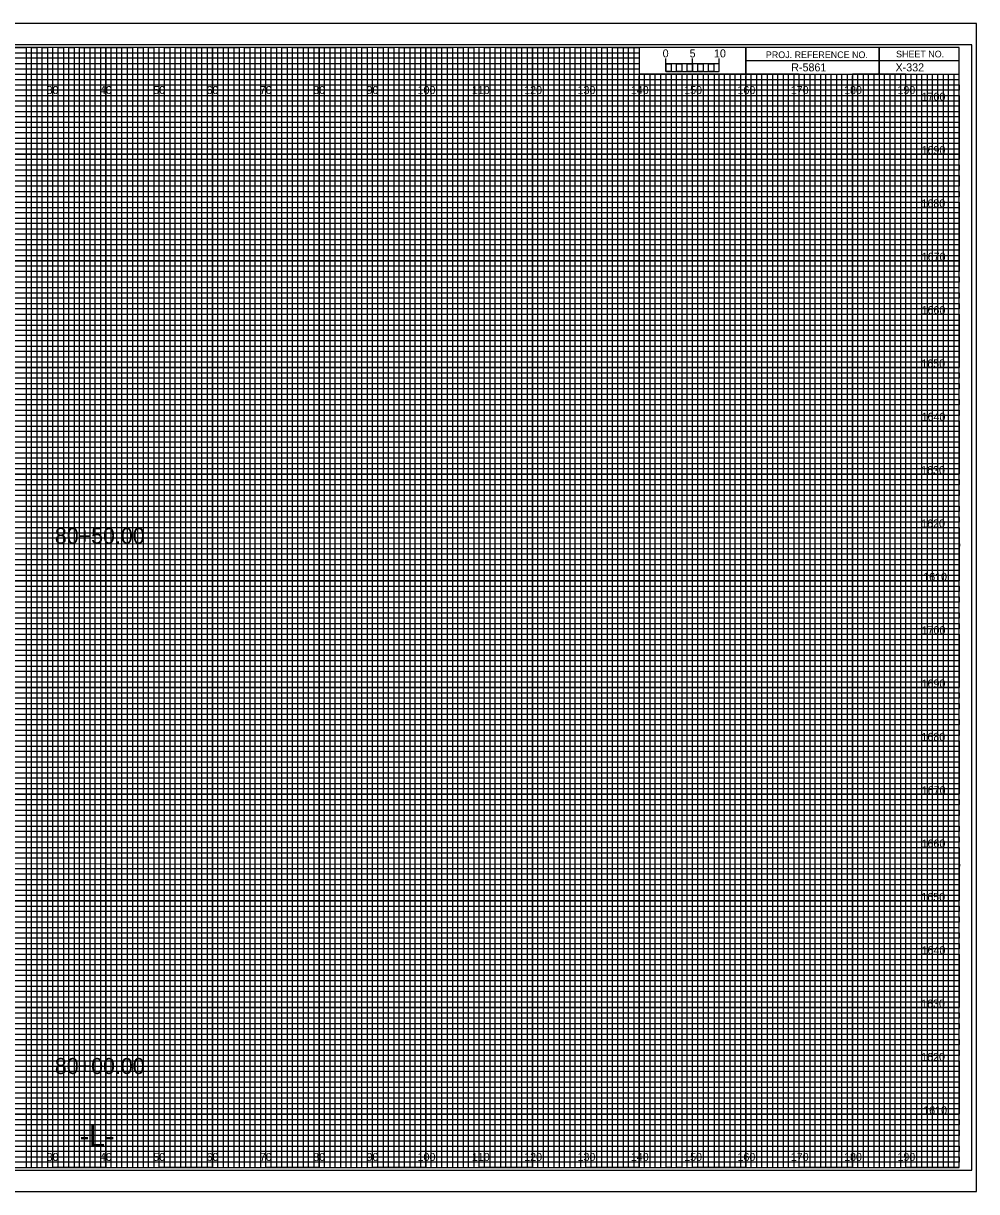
# Model space of a CAD drawing. Extents: x -13 to 1780, y -15 to 3284.
# Drawn here: x 144.5 to 323.3, y -4.5 to 214.5 of the extents above; entities that cross this region are included whole.
import ezdxf

# ---------------------------------------------------------------- set-up
doc = ezdxf.new("R2010")
doc.units = 0
for name, color, linetype in [('Exist CMT Pavement', 7, 'Continuous'), ('Prop Horizontal Alignment', 7, 'Continuous'), ('Prop Retaining Wall', 7, 'Continuous'), ('Prop SS Cut Line', 7, 'Continuous'), ('Prop SS Fill Line', 7, 'Continuous'), ('Prop SS Transition Line', 7, 'Continuous'), ('Prop XS Bar Scale Labels', 7, 'Continuous'), ('Prop XS DDE', 7, 'Continuous'), ('Prop XS Earthwork Shape', 7, 'Continuous'), ('Prop XS Noise Wall', 7, 'Continuous'), ('Prop XS Retaining Wall', 7, 'Continuous'), ('Prop XS Station Labels', 7, 'Continuous'), ('Raster_Level_0', 7, 'Continuous'), ('Scratch_Level_3', 7, 'Continuous'), ('Scratch_Level_7', 7, 'Continuous'), ('Typical Bridge Rail CELL', 7, 'Continuous'), ('Typical Median Barrier CELL', 7, 'Continuous')]:
    doc.layers.add(name, color=color, linetype=linetype)

msp = doc.modelspace()

# ---------------------------------------------------------------- linework, layer by layer
at = {"layer": 'Prop Retaining Wall'}
for p, q in [((305, 210), (305, 205)), ((305, 205), (305, 210)), ((280, 207.5), (280, 205)), ((320, 207.49), (280, 207.49)), ((280, 205), (320, 205))]:
    msp.add_line(p, q, dxfattribs=at)
for points in [[(320, 210), (0, 210), (0, 0), (320, 0)], [(280, 210), (260, 210), (260, 205.03), (280, 205.03)], [(320, 210), (280, 210), (280, 205), (320, 205)]]:
    msp.add_lwpolyline(points, close=True, dxfattribs=at)
at = {"layer": 'Prop SS Cut Line'}
for points in [[(135, 210), (145, 210), (145, 0), (155, 0), (155, 210), (165, 210), (165, 0), (175, 0), (175, 210), (185, 210), (185, 0), (195, 0), (195, 210), (205, 210), (205, 0), (215, 0), (215, 210), (225, 210), (225, 0), (235, 0), (235, 210), (245, 210), (245, 0), (255, 0), (255, 210), (259.93, 210), (260, 210), (260, 205), (264.99, 205), (264.99, 0), (275, 0), (275, 205), (285, 205), (285, 0), (295, 0), (295, 205), (305, 205), (305, 0), (315, 0), (315, 205)], [(0, 205), (275, 205)], [(0, 185), (320, 185), (320, 195), (0, 195)], [(0, 165), (320, 165), (320, 175), (0, 175)], [(0, 145), (320, 145), (320, 155), (0, 155)], [(0, 125), (320, 125), (320, 135), (0, 135)], [(0, 105), (320, 105), (320, 115), (0, 115)], [(0, 85), (320, 85), (320, 95), (0, 95)], [(0, 65), (320, 65), (320, 75), (0, 75)], [(0, 45), (320, 45), (320, 55), (0, 55)], [(0, 25), (320, 25), (320, 35), (0, 35)], [(0, 5), (320, 5), (320, 15), (0, 15)]]:
    msp.add_lwpolyline(points, dxfattribs=at)
at = {"layer": 'Prop SS Fill Line'}
for p, q in [((150, 210), (140, 210)), ((150, 0), (150, 210)), ((170, 210), (160, 210)), ((160, 210), (160, 0)), ((170, 0), (170, 210)), ((190, 210), (180, 210)), ((180, 210), (180, 0)), ((190, 0), (190, 210)), ((210, 210), (200, 210)), ((200, 210), (200, 0)), ((210, 0), (210, 210)), ((230, 210), (220, 210)), ((220, 210), (220, 0)), ((230, 0), (230, 210)), ((250, 210), (240, 210)), ((240, 210), (240, 0)), ((250, 0), (250, 210)), ((260, 210), (260, 0)), ((270, 0), (270, 205)), ((290, 205), (280, 205)), ((280, 205), (280, 0)), ((290, 0), (290, 205)), ((310, 205), (300, 205)), ((300, 205), (300, 0)), ((310, 0), (310, 205)), ((160, 0), (150, 0)), ((180, 0), (170, 0)), ((200, 0), (190, 0)), ((220, 0), (210, 0)), ((240, 0), (230, 0)), ((260, 0), (250, 0)), ((280, 0), (270, 0)), ((300, 0), (290, 0)), ((320, 0), (310, 0)), ((320, 0), (320, 0))]:
    msp.add_line(p, q, dxfattribs=at)
for points in [[(0, 200), (320, 200), (320, 190), (0, 190)], [(0, 180), (320, 180), (320, 170), (0, 170)], [(0, 160), (320, 160), (320, 150), (0, 150)], [(0, 140), (320, 140), (320, 130), (0, 130)], [(0, 120), (320, 120), (320, 110), (0, 110)], [(0, 100), (320, 100), (320, 90), (0, 90)], [(0, 80), (320, 80), (320, 70), (0, 70)], [(0, 60), (320, 60), (320, 50), (0, 50)], [(0, 40), (320, 40), (320, 30), (0, 30)], [(0, 20), (320, 20), (320, 10), (0, 10)]]:
    msp.add_lwpolyline(points, dxfattribs=at)
at = {"layer": 'Prop SS Transition Line'}
for p, q in [((0, 209), (260, 209)), ((260, 209), (260, 207.98)), ((260, 207.98), (0, 207.98)), ((0, 207), (260, 207)), ((260, 205.89), (0, 205.89)), ((260, 207), (260, 205.89)), ((0, 204), (320, 204))]:
    msp.add_line(p, q, dxfattribs=at)
for points in [[(0, 203), (270, 203), (320, 203), (320, 202), (0, 202)], [(0, 201), (320, 201), (320, 199), (0, 199)], [(0, 198), (320, 198), (320, 197), (0, 196.98)], [(0, 196), (320, 196), (320, 194), (0, 194)], [(0, 193), (320, 193), (320, 192), (0, 192)], [(0, 191), (320, 191), (320, 189), (0, 189)], [(0, 188), (320, 188), (320, 187), (0, 187)], [(0, 186), (320, 186), (320, 184), (0, 184)], [(0, 183), (320, 183), (320, 182), (0, 182)], [(0, 181), (320, 181), (320, 179), (0, 179)], [(0, 178), (320, 178), (320, 177), (0, 177)], [(0, 176), (320, 176), (320, 173.95), (320, 173), (320, 172), (0, 172)], [(0, 174), (320, 174), (320, 173), (0, 173)], [(0, 171), (320, 171), (320, 169), (0, 169.03)], [(0, 169.03), (320, 169), (320, 168), (0, 168)], [(0, 167), (320, 167), (320, 166), (0, 166)], [(0, 164), (320, 164), (320, 163), (0, 163)], [(0, 162), (320, 162), (320, 161), (0, 161)], [(-0.07, 158.89), (320, 158.89), (320, 157.88), (-0.07, 157.88)], [(0, 157), (320, 157), (320, 156), (0, 156)], [(0, 154), (320, 154), (320, 153), (0, 153)], [(0, 152), (320, 152), (320, 151), (0, 151)], [(0, 149), (320, 149), (320, 148), (0, 148)], [(0, 147), (320, 147), (320, 146), (0, 146)], [(0, 144), (320, 144), (320, 143), (0, 143)], [(0, 142), (320, 142), (320, 141), (0, 141)], [(0, 139), (320, 139), (319.99, 137.98), (0, 138)], [(0, 137), (320, 137), (320, 136), (0, 136)], [(0, 134), (320, 134), (320, 133), (0, 133)], [(0, 132), (320, 132), (320, 131), (0, 131)], [(0, 129), (320, 129), (320, 128), (0, 128)], [(0, 127), (320, 127), (320, 126), (0, 126)], [(0, 124), (320, 124), (320, 123), (0, 123)], [(0, 122), (320, 122), (320, 121), (0, 121)], [(0, 119), (320, 119), (320, 118), (0, 118)], [(0, 116.99), (320.07, 116.91), (320, 116), (0, 116)], [(0, 114), (320, 114), (320, 113), (0, 113)], [(0, 112), (320, 112), (320, 111), (0, 111)], [(0, 109), (320, 109), (320, 108), (0, 108)], [(0, 107), (320, 107), (320, 106), (0, 106)], [(0, 104), (320, 104), (320, 103), (0, 103)], [(0, 102), (320, 102), (320, 101), (0, 101)], [(0, 99), (320, 99), (320, 98), (0, 98)], [(0, 97), (320, 97), (320, 96), (0, 96)], [(0, 94), (320, 94), (320, 93), (0, 93)], [(0, 92), (320, 92), (320, 91), (0, 91)], [(0, 89), (320, 89), (320, 88), (0, 88)], [(0, 87), (320, 87), (320, 86), (0, 86)], [(0, 84), (320, 84), (320, 83), (0, 83)], [(0, 82), (320, 82), (320, 81), (0, 81)], [(0, 79), (320, 79), (319.99, 77.98), (0, 78)], [(0, 77), (320, 77), (320, 76), (0, 76)], [(0, 74), (320, 74), (320, 73), (0, 73)], [(0, 72), (320, 72), (320, 71), (0, 71)], [(0, 69), (320, 69), (320, 68), (0, 68)], [(0, 67), (320, 67), (320, 66), (0, 66)], [(0, 64), (320, 64), (320, 63), (0, 63)], [(0, 62), (320, 62), (320, 61), (0, 61)], [(0, 59), (320, 59), (320, 58), (0, 58)], [(0, 56.99), (320.07, 56.91), (320, 56), (0, 56)], [(0, 54), (320, 54), (320, 53), (0, 53)], [(0, 52), (320, 52), (320, 51), (0, 51)], [(0, 49), (320, 49), (320, 48), (0, 48)], [(0, 47), (320, 47), (320, 46), (0, 46)], [(0, 44), (320, 44), (320, 43), (0, 43)], [(0, 42), (320, 42), (320, 41), (0, 41)], [(0, 39), (320, 39), (320, 38), (0, 38)], [(0, 37), (320, 37), (320, 36), (0, 36)], [(0, 34), (320, 34), (320, 33), (0, 33)], [(0, 32), (320, 32), (320, 31), (0, 31)], [(0, 29), (320, 29), (320, 28), (0, 28)], [(0, 27), (320, 27), (320, 26), (0, 26)], [(0, 24), (320, 24), (320, 23), (0, 23)], [(0, 22), (320, 22), (320, 21), (0, 21)], [(0, 19), (320, 19), (320, 18), (0, 18)], [(0, 17), (320, 17), (320, 16), (0, 16)], [(0, 14), (320, 14), (320, 13), (0, 13)], [(0, 12), (320, 12), (320, 11), (0, 11)], [(0, 9), (320, 9), (320, 8), (0, 8)], [(0, 7), (320, 7), (320, 6), (0, 6)], [(0, 4), (320, 4), (320, 3), (0, 3)], [(0, 2), (320, 2), (320, 1), (0, 1)]]:
    msp.add_lwpolyline(points, dxfattribs=at)
at = {"layer": 'Prop XS Earthwork Shape'}
msp.add_lwpolyline([(-13.4, -4.5), (323.3, -4.5), (323.3, 214.5), (-13.4, 214.5)], close=True, dxfattribs=at)
at = {"layer": 'Prop XS Noise Wall'}
for p, q in [((150, 0), (150, 210)), ((160, 0), (160, 210)), ((170, 0), (170, 210)), ((180, 0), (180, 210)), ((190, 0), (190, 210)), ((200, 0), (200, 210)), ((210, 0), (210, 210)), ((220, 0), (220, 210)), ((230, 0), (230, 210)), ((240, 0), (240, 210)), ((250, 0), (250, 210)), ((260, 0), (260, 204.69)), ((270, 0), (270, 204.69)), ((280, 0), (280, 204.69)), ((290, 0), (290, 204.69)), ((300, 0), (300, 204.69)), ((310, 0), (310, 204.69)), ((0, 200), (320, 200)), ((0, 190), (320, 190)), ((0, 180), (320, 180)), ((0, 170), (320, 170)), ((0, 160), (320, 160)), ((0, 150), (320, 150)), ((0, 140), (320, 140)), ((0, 130), (320, 130)), ((0, 120), (320, 120)), ((0, 110), (320, 110)), ((0, 100), (320, 100)), ((0, 90), (320, 90)), ((0, 80), (320, 80)), ((0, 70), (320, 70)), ((0, 60), (320, 60)), ((0, 50), (320, 50)), ((0, 40), (320, 40)), ((0, 30), (320, 30)), ((0, 20), (320, 20)), ((0, 10), (320, 10))]:
    msp.add_line(p, q, dxfattribs=at)
at = {"layer": 'Prop XS Retaining Wall'}
for p, q in [((265, 205.49), (265, 207.9)), ((265, 206.9), (265, 207.9)), ((270, 205.49), (270, 207.9)), ((275, 205.49), (275, 207.9)), ((275, 206.9), (275, 207.9))]:
    msp.add_line(p, q, dxfattribs=at)
for points in [[(275, 206.9), (265, 206.9), (265, 205.49), (275, 205.49)], [(265, 206.9), (266, 206.9), (266, 205.49), (265, 205.49)], [(267, 206.9), (268, 206.9), (268, 205.49), (267, 205.49)], [(269, 206.9), (270, 206.9), (270, 205.49), (269, 205.49)], [(271, 206.9), (272, 206.9), (272, 205.49), (271, 205.49)], [(273, 206.9), (274, 206.9), (274, 205.49), (273, 205.49)]]:
    msp.add_lwpolyline(points, close=True, dxfattribs=at)
at = {"layer": 'Prop XS Station Labels'}
for p, q in [((323.3, 214.5), (-13.4, 214.5)), ((-13.4, -4.5), (323.3, -4.5))]:
    msp.add_line(p, q, dxfattribs=at)
at = {"layer": 'Scratch_Level_7'}
msp.add_lwpolyline([(-10.8, -0.5), (322.4, -0.5), (322.4, 210.5), (-10.8, 210.5)], close=True, dxfattribs=at)
at = {"layer": 'Typical Bridge Rail CELL'}
for p, q in [((267, 205), (266.01, 205)), ((266.01, 205), (266.01, 0)), ((267, 0), (267, 205)), ((269, 205), (268, 205)), ((268, 205), (268, 0)), ((269, 0), (269, 205)), ((266.01, 0), (265, 0)), ((268, 0), (267, 0))]:
    msp.add_line(p, q, dxfattribs=at)
for points in [[(145, 0), (146, 0), (146, 210), (147, 210), (147, 0)], [(147, 0), (148, 0), (148, 210), (149, 210), (149, 0)], [(150, 0), (151, 0), (151, 210), (152, 210), (152, 0)], [(152, 0), (153, 0), (153, 210), (154, 210), (154, 0)], [(155, 0), (156, 0), (156, 210), (157, 210), (157, 0)], [(157, 0), (158, 0), (158, 210), (159, 210), (159, 0)], [(160, 0), (161, 0), (161, 210), (162, 210), (162, 0)], [(162, 0), (163, 0), (163, 210), (164, 210), (164, 0)], [(165, 0), (166, 0), (166, 210), (167, 210), (167, 0)], [(167, 0), (168, 0), (168, 210), (169, 210), (169, 0)], [(170, 0), (171, 0), (171, 210), (172, 210), (172, 0)], [(172, 0), (173, 0), (173, 210), (174, 210), (174, 0)], [(175, 0), (176, 0), (176, 210), (177, 210), (177, 0)], [(177, 0), (178, 0), (178, 210), (179, 210), (179, 0)], [(180, 0), (181, 0), (181, 210), (182, 210), (182, 0)], [(182, 0), (183, 0), (183, 210), (184, 210), (184, 0)], [(185, 0), (186, 0), (186, 210), (187, 210), (187, 0)], [(187, 0), (188, 0), (188, 210), (189, 210), (189, 0)], [(190, 0), (191, 0), (191, 210), (192, 210), (192, 0)], [(192, 0), (193, 0), (193, 210), (194, 210), (194, 0)], [(195, 0), (196, 0), (196, 210), (197, 210), (197, 0)], [(197, 0), (198, 0), (198, 210), (199, 210), (199, 0)], [(200, 0), (201, 0), (201, 210), (202, 210), (202, 0)], [(202, 0), (203, 0), (203, 210), (204, 210), (204, 0)], [(205, 0), (206, 0), (206, 210), (207, 210), (207, 0)], [(207, 0), (208, 0), (208, 210), (209, 210), (209, 0)], [(210, 0), (211, 0), (211, 210), (212, 210), (212, 0)], [(212, 0), (213, 0), (213, 210), (214, 210), (214, 0)], [(215, 0), (216, 0), (216, 210), (217, 210), (217, 0)], [(217, 0), (218, 0), (218, 210), (219, 210), (219, 0)], [(220, 0), (221, 0), (221, 210), (222, 210), (222, 0)], [(222, 0), (223, 0), (223, 210), (224, 210), (224, 0)], [(225, 0), (226, 0), (226, 210), (227, 210), (227, 0)], [(227, 0), (228, 0), (228, 210), (229, 210), (229, 0)], [(230, 0), (231, 0), (231, 210), (232, 210), (232, 0)], [(232, 0), (233, 0), (233, 210), (234, 210), (234, 0)], [(235, 0), (236, 0), (236, 210), (237, 210), (237, 0)], [(237, 0), (238, 0), (238, 210), (239, 210), (239, 0)], [(240, 0), (241, 0), (241, 210), (242, 210), (242, 0)], [(242, 0), (243, 0), (243, 210), (244, 210), (244, 0)], [(245, 0), (246, 0), (246, 210), (247, 210), (247, 0)], [(247, 0), (248, 0), (248, 210), (249, 210), (249, 0)], [(250, 0), (251, 0), (251, 210), (252, 210), (252, 0)], [(252, 0), (253, 0), (253, 210), (254, 210), (254, 0)], [(255, 0), (256, 0), (256, 210), (257, 210), (257, 0)], [(257, 0), (258, 0), (258, 210), (259, 210), (259, 0)], [(260, 0), (261, 0), (261, 205), (262.02, 205), (262.02, 0)], [(262, 0), (263, 0), (263, 205), (263.99, 205), (263.99, 0)], [(270, 0), (270.98, 0), (270.98, 205), (272, 205), (272, 0)], [(272, 0), (273, 0), (273, 205), (274.05, 205), (274.05, 0)], [(275, 0), (276, 0), (276, 205), (277, 205), (277, 0)], [(277, 0), (278, 0), (278, 205), (279, 205), (279, 0)], [(280, 0), (281, 0), (281, 205), (282, 205), (282, 0)], [(282, 0), (283, 0), (283, 205), (284, 205), (284, 0)], [(285, 0), (286, 0), (286, 205), (287, 205), (287, 0)], [(287, 0), (288, 0), (288, 205), (289, 205), (289, 0)], [(290, 0), (291, 0), (291, 205), (292, 205), (292, 0)], [(292, 0), (293, 0), (293, 205), (294, 205), (294, 0)], [(295, 0), (296, 0), (296, 205), (297, 205), (297, 0)], [(297, 0), (298, 0), (298, 205), (299, 205), (299, 0)], [(300, 0), (301, 0), (301, 205), (302, 205), (302, 0)], [(302, 0), (303, 0), (303, 205), (304, 205), (304, 0)], [(305, 0), (306, 0), (306, 205), (307, 205), (307, 0)], [(307, 0), (308, 0), (308, 205), (309, 205), (309, 0)], [(310, 0), (311, 0), (311, 205), (312, 205), (312, 0)], [(312, 0), (313, 0), (313, 205), (314, 205), (314, 0)], [(315, 0), (316, 0), (316, 205), (317, 205), (317, 0)], [(317, 0), (318, 0), (318, 205), (319, 205), (319, 0)]]:
    msp.add_lwpolyline(points, dxfattribs=at)

# ---------------------------------------------------------------- texts
at = {"layer": 'Exist CMT Pavement'}
msp.add_text('R-5861', height=1.5, dxfattribs=at).set_placement((288.53, 205.5))
at = {"layer": 'Prop Horizontal Alignment'}
for s, p in [('80+50.00', (150.41, 116.95)), ('80+00.00', (150.41, 17.55))]:
    msp.add_text(s, height=3, dxfattribs=at).set_placement(p)
at = {"layer": 'Prop Retaining Wall'}
for s, p in [('PROJ. REFERENCE NO.', (283.77, 207.99)), ('SHEET NO.', (308.19, 208.12))]:
    msp.add_text(s, height=1.25, dxfattribs=at).set_placement(p)
at = {"layer": 'Prop XS Bar Scale Labels'}
for s, p in [('5', (269.47, 208.12)), ('10', (274.04, 208.12))]:
    msp.add_text(s, height=1.5, dxfattribs=at).set_placement(p)
at = {"layer": 'Prop XS DDE'}
msp.add_text('-L-', height=4, dxfattribs=at).set_placement((155.06, 4))
at = {"layer": 'Prop XS Retaining Wall'}
msp.add_text('0', height=1.5, dxfattribs=at).set_placement((264.41, 208.12))
at = {"layer": 'Raster_Level_0'}
for s, p in [('30', (148.86, 201.25)), ('40', (158.86, 201.25)), ('50', (168.86, 201.25)), ('60', (178.86, 201.25)), ('70', (188.86, 201.25)), ('80', (198.86, 201.25)), ('90', (208.86, 201.25)), ('100', (218.44, 201.25)), ('110', (228.62, 201.25)), ('120', (238.44, 201.25)), ('130', (248.44, 201.25)), ('140', (258.44, 201.25)), ('150', (268.44, 201.25)), ('160', (278.44, 201.25)), ('170', (288.44, 201.25)), ('180', (298.44, 201.25)), ('190', (308.44, 201.25)), ('30', (148.86, 1.25)), ('40', (158.86, 1.25)), ('50', (168.86, 1.25)), ('60', (178.86, 1.25)), ('70', (188.86, 1.25)), ('80', (198.86, 1.25)), ('90', (208.86, 1.25)), ('100', (218.44, 1.25)), ('110', (228.62, 1.25)), ('120', (238.44, 1.25)), ('130', (248.44, 1.25)), ('140', (258.44, 1.25)), ('150', (268.44, 1.25)), ('160', (278.44, 1.25)), ('170', (288.44, 1.25)), ('180', (298.44, 1.25)), ('190', (308.44, 1.25))]:
    msp.add_text(s, height=1.5, dxfattribs=at).set_placement(p)
at = {"layer": 'Scratch_Level_3'}
for s, p in [('1700', (312.98, 200)), ('1690', (312.97, 190)), ('1680', (312.95, 180)), ('1670', (313, 170)), ('1660', (312.97, 160)), ('1650', (312.92, 150)), ('1640', (312.97, 140)), ('1630', (312.89, 130)), ('1620', (312.9, 120)), ('1610', (313.28, 110)), ('1700', (312.98, 100)), ('1690', (312.97, 90)), ('1680', (312.95, 80)), ('1670', (313, 70)), ('1660', (312.97, 60)), ('1650', (312.92, 50)), ('1640', (312.97, 40)), ('1630', (312.89, 30)), ('1620', (312.9, 20)), ('1610', (313.28, 10))]:
    msp.add_text(s, height=1.5, dxfattribs=at).set_placement(p)
at = {"layer": 'Typical Median Barrier CELL'}
msp.add_text('X-332', height=1.5, dxfattribs=at).set_placement((308.09, 205.5))

doc.saveas('drawing.dxf')
